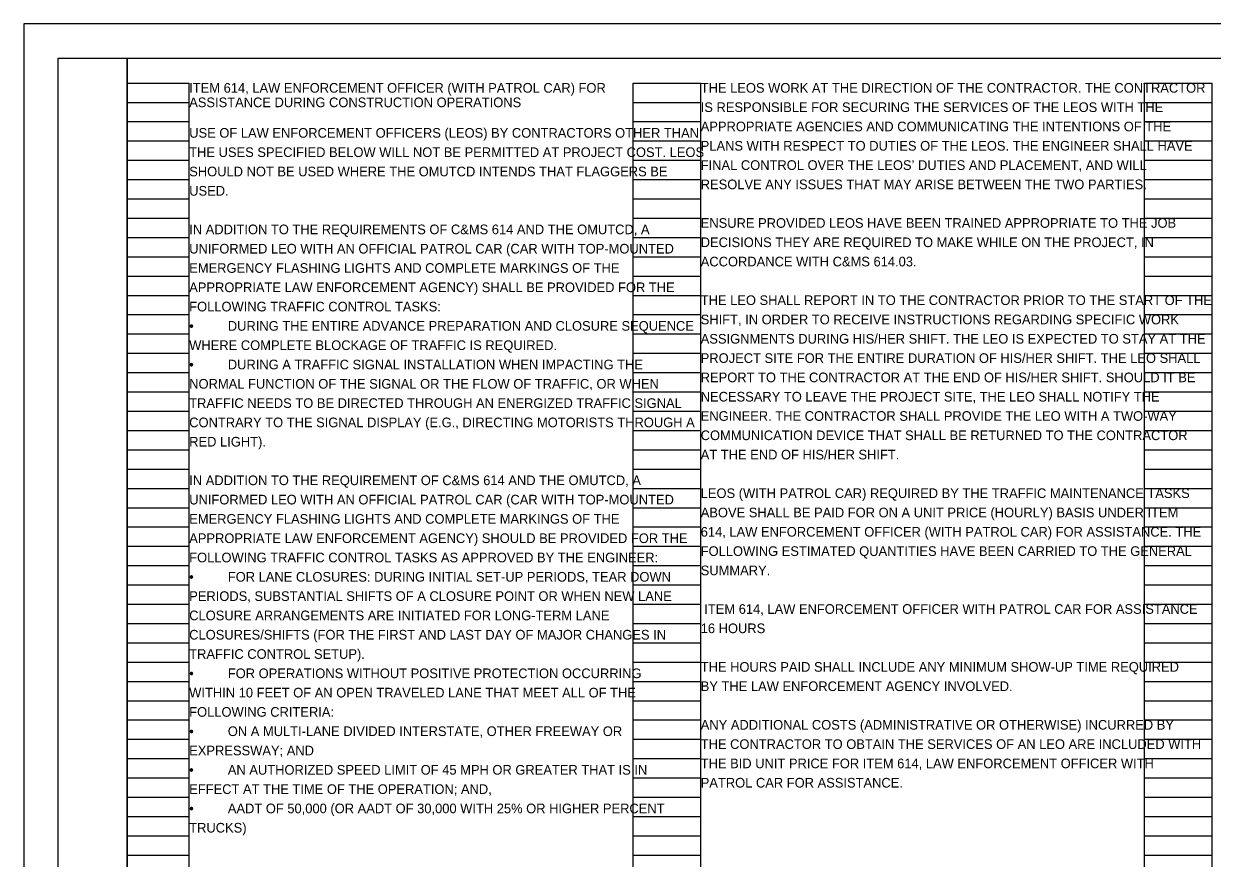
# Model space of a CAD drawing. Extents: x -1.3 to 43.7, y -2.4 to 22.
# Drawn here: x 0 to 17.24, y 9.89 to 22 of the extents above; entities that cross this region are included whole.
import ezdxf

# ---------------------------------------------------------------- set-up
doc = ezdxf.new("R2010")
doc.units = 0
for name, color, linetype in [('SH_Border', 7, 'Continuous'), ('SH_Cut_Line', 7, 'Continuous'), ('SH_Data', 7, 'Continuous'), ('SH_Text', 7, 'Continuous')]:
    doc.layers.add(name, color=color, linetype=linetype)

msp = doc.modelspace()

# ---------------------------------------------------------------- linework, layer by layer
at = {"layer": 'SH_Border'}
for points in [[(0.5, 21.5), (1.5, 21.5), (1.5, 0.5), (0.5, 0.5)], [(1.5, 21.5), (33.5, 21.5), (33.5, 0.5), (1.5, 0.5)]]:
    msp.add_lwpolyline(points, close=True, dxfattribs=at)
at = {"layer": 'SH_Cut_Line'}
msp.add_lwpolyline([(0, 0), (34, 0), (34, 22), (0, 22)], close=True, dxfattribs=at)
at = {"layer": 'SH_Data'}
for p, q in [((1.5, 0.98), (1.5, 21.14)), ((1.5, 21.14), (2.4, 21.14)), ((2.4, 0.98), (2.4, 21.14)), ((8.84, 0.98), (8.84, 21.14)), ((8.84, 21.14), (9.82, 21.14)), ((9.82, 0.98), (9.82, 21.14)), ((16.26, 0.98), (16.26, 21.14)), ((16.26, 21.14), (17.24, 21.14)), ((17.24, 0.98), (17.24, 21.14)), ((1.5, 20.86), (2.4, 20.86)), ((8.84, 20.86), (9.82, 20.86)), ((16.26, 20.86), (17.24, 20.86)), ((1.5, 20.58), (2.4, 20.58)), ((8.84, 20.58), (9.82, 20.58)), ((16.26, 20.58), (17.24, 20.58)), ((1.5, 20.3), (2.4, 20.3)), ((8.84, 20.3), (9.82, 20.3)), ((16.26, 20.3), (17.24, 20.3)), ((1.5, 20.02), (2.4, 20.02)), ((8.84, 20.02), (9.82, 20.02)), ((16.26, 20.02), (17.24, 20.02)), ((1.5, 19.74), (2.4, 19.74)), ((8.84, 19.74), (9.82, 19.74)), ((16.26, 19.74), (17.24, 19.74)), ((1.5, 19.46), (2.4, 19.46)), ((8.84, 19.46), (9.82, 19.46)), ((16.26, 19.46), (17.24, 19.46)), ((1.5, 19.18), (2.4, 19.18)), ((8.84, 19.18), (9.82, 19.18)), ((16.26, 19.18), (17.24, 19.18)), ((1.5, 18.9), (2.4, 18.9)), ((8.84, 18.9), (9.82, 18.9)), ((16.26, 18.9), (17.24, 18.9)), ((1.5, 18.62), (2.4, 18.62)), ((8.84, 18.62), (9.82, 18.62)), ((16.26, 18.62), (17.24, 18.62)), ((1.5, 18.34), (2.4, 18.34)), ((8.84, 18.34), (9.82, 18.34)), ((16.26, 18.34), (17.24, 18.34)), ((1.5, 18.06), (2.4, 18.06)), ((8.84, 18.06), (9.82, 18.06)), ((16.26, 18.06), (17.24, 18.06)), ((1.5, 17.78), (2.4, 17.78)), ((8.84, 17.78), (9.82, 17.78)), ((16.26, 17.78), (17.24, 17.78)), ((1.5, 17.5), (2.4, 17.5)), ((8.84, 17.5), (9.82, 17.5)), ((16.26, 17.5), (17.24, 17.5)), ((1.5, 17.22), (2.4, 17.22)), ((8.84, 17.22), (9.82, 17.22)), ((16.26, 17.22), (17.24, 17.22)), ((1.5, 16.94), (2.4, 16.94)), ((8.84, 16.94), (9.82, 16.94)), ((16.26, 16.94), (17.24, 16.94)), ((1.5, 16.66), (2.4, 16.66)), ((8.84, 16.66), (9.82, 16.66)), ((16.26, 16.66), (17.24, 16.66)), ((1.5, 16.38), (2.4, 16.38)), ((8.84, 16.38), (9.82, 16.38)), ((16.26, 16.38), (17.24, 16.38)), ((1.5, 16.1), (2.4, 16.1)), ((8.84, 16.1), (9.82, 16.1)), ((16.26, 16.1), (17.24, 16.1)), ((1.5, 15.82), (2.4, 15.82)), ((8.84, 15.82), (9.82, 15.82)), ((16.26, 15.82), (17.24, 15.82)), ((1.5, 15.54), (2.4, 15.54)), ((8.84, 15.54), (9.82, 15.54)), ((16.26, 15.54), (17.24, 15.54)), ((1.5, 15.26), (2.4, 15.26)), ((8.84, 15.26), (9.82, 15.26)), ((16.26, 15.26), (17.24, 15.26)), ((1.5, 14.98), (2.4, 14.98)), ((8.84, 14.98), (9.82, 14.98)), ((16.26, 14.98), (17.24, 14.98)), ((1.5, 14.7), (2.4, 14.7)), ((8.84, 14.7), (9.82, 14.7)), ((16.26, 14.7), (17.24, 14.7)), ((1.5, 14.42), (2.4, 14.42)), ((8.84, 14.42), (9.82, 14.42)), ((16.26, 14.42), (17.24, 14.42)), ((1.5, 14.14), (2.4, 14.14)), ((8.84, 14.14), (9.82, 14.14)), ((16.26, 14.14), (17.24, 14.14)), ((1.5, 13.86), (2.4, 13.86)), ((8.84, 13.86), (9.82, 13.86)), ((16.26, 13.86), (17.24, 13.86)), ((1.5, 13.58), (2.4, 13.58)), ((8.84, 13.58), (9.82, 13.58)), ((16.26, 13.58), (17.24, 13.58)), ((1.5, 13.3), (2.4, 13.3)), ((8.84, 13.3), (9.82, 13.3)), ((16.26, 13.3), (17.24, 13.3)), ((1.5, 13.02), (2.4, 13.02)), ((8.84, 13.02), (9.82, 13.02)), ((16.26, 13.02), (17.24, 13.02)), ((1.5, 12.74), (2.4, 12.74)), ((8.84, 12.74), (9.82, 12.74)), ((16.26, 12.74), (17.24, 12.74)), ((1.5, 12.46), (2.4, 12.46)), ((8.84, 12.46), (9.82, 12.46)), ((16.26, 12.46), (17.24, 12.46)), ((1.5, 12.18), (2.4, 12.18)), ((8.84, 12.18), (9.82, 12.18)), ((16.26, 12.18), (17.24, 12.18)), ((1.5, 11.9), (2.4, 11.9)), ((8.84, 11.9), (9.82, 11.9)), ((16.26, 11.9), (17.24, 11.9)), ((1.5, 11.62), (2.4, 11.62)), ((8.84, 11.62), (9.82, 11.62)), ((16.26, 11.62), (17.24, 11.62)), ((1.5, 11.34), (2.4, 11.34)), ((8.84, 11.34), (9.82, 11.34)), ((16.26, 11.34), (17.24, 11.34)), ((1.5, 11.06), (2.4, 11.06)), ((8.84, 11.06), (9.82, 11.06)), ((16.26, 11.06), (17.24, 11.06)), ((1.5, 10.78), (2.4, 10.78)), ((8.84, 10.78), (9.82, 10.78)), ((16.26, 10.78), (17.24, 10.78)), ((1.5, 10.5), (2.4, 10.5)), ((8.84, 10.5), (9.82, 10.5)), ((16.26, 10.5), (17.24, 10.5)), ((1.5, 10.22), (2.4, 10.22)), ((8.84, 10.22), (9.82, 10.22)), ((16.26, 10.22), (17.24, 10.22)), ((1.5, 9.94), (2.4, 9.94)), ((8.84, 9.94), (9.82, 9.94)), ((16.26, 9.94), (17.24, 9.94))]:
    msp.add_line(p, q, dxfattribs=at)

# ---------------------------------------------------------------- texts
at = {"layer": 'SH_Text'}
for s, p in [('ITEM 614, LAW ENFORCEMENT OFFICER (WITH PATROL CAR) FOR ', (2.4, 21)), ('THE LEOS WORK AT THE DIRECTION OF THE CONTRACTOR. THE CONTRACTOR ', (9.82, 21)), ('ASSISTANCE DURING CONSTRUCTION OPERATIONS', (2.4, 20.79)), ('IS RESPONSIBLE FOR SECURING THE SERVICES OF THE LEOS WITH THE ', (9.82, 20.72)), ('APPROPRIATE AGENCIES AND COMMUNICATING THE INTENTIONS OF THE ', (9.82, 20.44)), ('USE OF LAW ENFORCEMENT OFFICERS (LEOS) BY CONTRACTORS OTHER THAN ', (2.4, 20.347)), ('THE USES SPECIFIED BELOW WILL NOT BE PERMITTED AT PROJECT COST. LEOS ', (2.4, 20.067)), ('PLANS WITH RESPECT TO DUTIES OF THE LEOS. THE ENGINEER SHALL HAVE ', (9.82, 20.16)), ('FINAL CONTROL OVER THE LEOS’ DUTIES AND PLACEMENT, AND WILL ', (9.82, 19.88)), ('SHOULD NOT BE USED WHERE THE OMUTCD INTENDS THAT FLAGGERS BE ', (2.4, 19.787)), ('RESOLVE ANY ISSUES THAT MAY ARISE BETWEEN THE TWO PARTIES. ', (9.82, 19.6)), ('USED.', (2.4, 19.507)), ('ENSURE PROVIDED LEOS HAVE BEEN TRAINED APPROPRIATE TO THE JOB ', (9.82, 19.04)), ('IN ADDITION TO THE REQUIREMENTS OF C&MS 614 AND THE OMUTCD, A ', (2.4, 18.947)), ('UNIFORMED LEO WITH AN OFFICIAL PATROL CAR (CAR WITH TOP-MOUNTED ', (2.4, 18.667)), ('DECISIONS THEY ARE REQUIRED TO MAKE WHILE ON THE PROJECT, IN ', (9.82, 18.76)), ('ACCORDANCE WITH C&MS 614.03. ', (9.82, 18.48)), ('EMERGENCY FLASHING LIGHTS AND COMPLETE MARKINGS OF THE ', (2.4, 18.387)), ('APPROPRIATE LAW ENFORCEMENT AGENCY) SHALL BE PROVIDED FOR THE ', (2.4, 18.107)), ('FOLLOWING TRAFFIC CONTROL TASKS:', (2.4, 17.827)), ('THE LEO SHALL REPORT IN TO THE CONTRACTOR PRIOR TO THE START OF THE ', (9.82, 17.92)), ('SHIFT, IN ORDER TO RECEIVE INSTRUCTIONS REGARDING SPECIFIC WORK ', (9.82, 17.64)), ('•', (2.4, 17.547)), ('DURING THE ENTIRE ADVANCE PREPARATION AND CLOSURE SEQUENCE ', (2.96, 17.547)), ('ASSIGNMENTS DURING HIS/HER SHIFT. THE LEO IS EXPECTED TO STAY AT THE ', (9.82, 17.36)), ('WHERE COMPLETE BLOCKAGE OF TRAFFIC IS REQUIRED. ', (2.4, 17.267)), ('•', (2.4, 16.987)), ('DURING A TRAFFIC SIGNAL INSTALLATION WHEN IMPACTING THE ', (2.96, 16.987)), ('PROJECT SITE FOR THE ENTIRE DURATION OF HIS/HER SHIFT. THE LEO SHALL ', (9.82, 17.08)), ('REPORT TO THE CONTRACTOR AT THE END OF HIS/HER SHIFT. SHOULD IT BE ', (9.82, 16.8)), ('NORMAL FUNCTION OF THE SIGNAL OR THE FLOW OF TRAFFIC, OR WHEN ', (2.4, 16.707)), ('TRAFFIC NEEDS TO BE DIRECTED THROUGH AN ENERGIZED TRAFFIC SIGNAL ', (2.4, 16.427)), ('NECESSARY TO LEAVE THE PROJECT SITE, THE LEO SHALL NOTIFY THE ', (9.82, 16.52)), ('ENGINEER. THE CONTRACTOR SHALL PROVIDE THE LEO WITH A TWO-WAY ', (9.82, 16.24)), ('CONTRARY TO THE SIGNAL DISPLAY (E.G., DIRECTING MOTORISTS THROUGH A ', (2.4, 16.147)), ('COMMUNICATION DEVICE THAT SHALL BE RETURNED TO THE CONTRACTOR ', (9.82, 15.96)), ('RED LIGHT). ', (2.4, 15.867)), ('AT THE END OF HIS/HER SHIFT.', (9.82, 15.68)), ('IN ADDITION TO THE REQUIREMENT OF C&MS 614 AND THE OMUTCD, A ', (2.4, 15.307)), ('UNIFORMED LEO WITH AN OFFICIAL PATROL CAR (CAR WITH TOP-MOUNTED ', (2.4, 15.027)), ('LEOS (WITH PATROL CAR) REQUIRED BY THE TRAFFIC MAINTENANCE TASKS ', (9.82, 15.12)), ('EMERGENCY FLASHING LIGHTS AND COMPLETE MARKINGS OF THE ', (2.4, 14.747)), ('ABOVE SHALL BE PAID FOR ON A UNIT PRICE (HOURLY) BASIS UNDER ITEM ', (9.82, 14.84)), ('614, LAW ENFORCEMENT OFFICER (WITH PATROL CAR) FOR ASSISTANCE. THE ', (9.82, 14.56)), ('APPROPRIATE LAW ENFORCEMENT AGENCY) SHOULD BE PROVIDED FOR THE ', (2.4, 14.467)), ('FOLLOWING TRAFFIC CONTROL TASKS AS APPROVED BY THE ENGINEER: ', (2.4, 14.187)), ('FOLLOWING ESTIMATED QUANTITIES HAVE BEEN CARRIED TO THE GENERAL ', (9.82, 14.28)), ('SUMMARY.', (9.82, 14)), ('•', (2.4, 13.907)), ('FOR LANE CLOSURES: DURING INITIAL SET-UP PERIODS, TEAR DOWN ', (2.96, 13.907)), ('PERIODS, SUBSTANTIAL SHIFTS OF A CLOSURE POINT OR WHEN NEW LANE ', (2.4, 13.627)), ('CLOSURE ARRANGEMENTS ARE INITIATED FOR LONG-TERM LANE ', (2.4, 13.347)), (' ITEM 614, LAW ENFORCEMENT OFFICER WITH PATROL CAR FOR ASSISTANCE ', (9.82, 13.44)), ('16 HOURS ', (9.82, 13.16)), ('CLOSURES/SHIFTS (FOR THE FIRST AND LAST DAY OF MAJOR CHANGES IN ', (2.4, 13.067)), ('TRAFFIC CONTROL SETUP).', (2.4, 12.787)), ('•', (2.4, 12.507)), ('FOR OPERATIONS WITHOUT POSITIVE PROTECTION OCCURRING ', (2.96, 12.507)), ('THE HOURS PAID SHALL INCLUDE ANY MINIMUM SHOW-UP TIME REQUIRED ', (9.82, 12.6)), ('BY THE LAW ENFORCEMENT AGENCY INVOLVED. ', (9.82, 12.32)), ('WITHIN 10 FEET OF AN OPEN TRAVELED LANE THAT MEET ALL OF THE ', (2.4, 12.227)), ('FOLLOWING CRITERIA:', (2.4, 11.947)), ('ANY ADDITIONAL COSTS (ADMINISTRATIVE OR OTHERWISE) INCURRED BY ', (9.82, 11.76)), ('•', (2.4, 11.667)), ('ON A MULTI-LANE DIVIDED INTERSTATE, OTHER FREEWAY OR ', (2.96, 11.667)), ('THE CONTRACTOR TO OBTAIN THE SERVICES OF AN LEO ARE INCLUDED WITH ', (9.82, 11.48)), ('EXPRESSWAY; AND', (2.4, 11.387)), ('AN AUTHORIZED SPEED LIMIT OF 45 MPH OR GREATER THAT IS IN ', (2.96, 11.107)), ('THE BID UNIT PRICE FOR ITEM 614, LAW ENFORCEMENT OFFICER WITH ', (9.82, 11.2)), ('•', (2.4, 11.107)), ('PATROL CAR FOR ASSISTANCE.', (9.82, 10.92)), ('EFFECT AT THE TIME OF THE OPERATION; AND,', (2.4, 10.827)), ('AADT OF 50,000 (OR AADT OF 30,000 WITH 25% OR HIGHER PERCENT ', (2.96, 10.547)), ('•', (2.4, 10.547)), ('TRUCKS)', (2.4, 10.267))]:
    msp.add_text(s, height=0.14, dxfattribs=at).set_placement(p)

doc.saveas('drawing.dxf')
